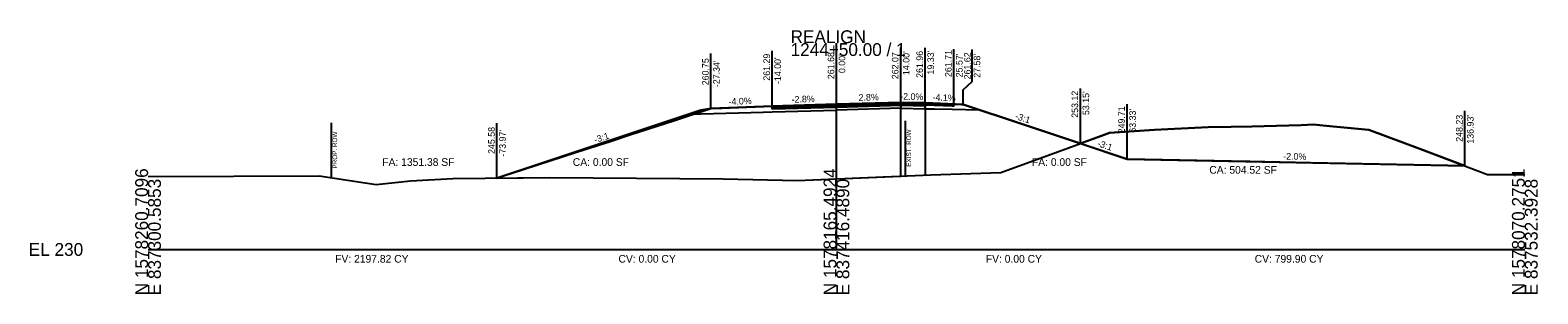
# Model space of a CAD drawing. Extents: x -26 to 6303, y -16 to 9563.
# Drawn here: x 1974.3 to 2302.8, y 5490.3 to 5547.8 of the extents above; entities that cross this region are included whole.
import ezdxf

# ---------------------------------------------------------------- set-up
doc = ezdxf.new("R2010")
doc.units = 0
for name, color, linetype in [('ASPHALT_19MM1', 7, 'Continuous'), ('ASPHALT_9_5MM1', 7, 'Continuous'), ('CONST_DCH', 7, 'Continuous'), ('CONST_LV3', 7, 'Continuous'), ('Draft_XS_Grid', 7, 'Continuous'), ('DTM_P_FINISHED_GRADE', 7, 'Continuous'), ('DTM_P_FINISHED_GRADE2', 7, 'Continuous'), ('DTM_TEMP_DROP', 7, 'Continuous'), ('DTM_X_GROUND', 7, 'Continuous'), ('TRANS_EOP_PAVED', 7, 'Continuous'), ('TRANS_PAVED_SHOULDERS', 7, 'Continuous'), ('XS_CELL', 7, 'Continuous'), ('XS_M_SHAPES_EARTHWORK', 7, 'Continuous'), ('XS_P_ASPHALT', 7, 'Continuous'), ('XS_P_GROUND', 7, 'Continuous'), ('XS_P_ROW', 7, 'Continuous'), ('XS_P_SHOULDER', 7, 'Continuous'), ('XS_P_SUBGRADE_GRANULAR', 7, 'Continuous'), ('XS_P_TX_CLEARZONE', 7, 'Continuous'), ('XS_P_TX_FS_BS', 7, 'Continuous'), ('XS_SHEET_EW_TX_AREA', 7, 'Continuous'), ('XS_SHEET_EW_TX_VOLUME', 7, 'Continuous'), ('XS_X_ROW', 7, 'Continuous')]:
    doc.layers.add(name, color=color, linetype=linetype)

msp = doc.modelspace()

# ---------------------------------------------------------------- linework, layer by layer
at = {"layer": 'ASPHALT_19MM1'}
for points in [[(2136, 5530.95), (2136, 5530.68), (2150, 5531.07), (2150, 5531.07), (2164, 5531.47), (2164, 5531.47), (2164, 5531.74), (2164, 5531.74), (2164, 5531.74), (2150, 5531.34), (2150, 5531.34), (2136, 5530.95), (2136, 5530.95)], [(2164, 5531.74), (2164, 5531.46), (2164, 5531.46), (2164, 5531.46), (2169.33, 5531.36), (2169.33, 5531.63), (2164, 5531.74), (2164, 5531.74), (2164, 5531.74)]]:
    msp.add_lwpolyline(points, dxfattribs=at)
at = {"layer": 'ASPHALT_9_5MM1'}
for points in [[(2136, 5531.29), (2136, 5531.16), (2150, 5531.55), (2150, 5531.55), (2164, 5531.94), (2164, 5531.94), (2164, 5532.07), (2164, 5532.07), (2164, 5532.07), (2150, 5531.68), (2150, 5531.68), (2136, 5531.29), (2136, 5531.29)], [(2164, 5532.07), (2164, 5531.94), (2164, 5531.94), (2164, 5531.94), (2169.33, 5531.84), (2169.33, 5531.96), (2164, 5532.07), (2164, 5532.07), (2164, 5532.07)]]:
    msp.add_lwpolyline(points, dxfattribs=at)
at = {"layer": 'CONST_LV3'}
for points in [[(2169.33, 5531.96), (2164, 5532.07), (2164, 5532.07), (2164, 5532.07), (2150, 5531.68)], [(2164, 5532.07), (2164, 5530.8), (2164, 5530.8), (2164, 5530.8), (2169.33, 5530.69), (2169.33, 5531.96), (2164, 5532.07), (2164, 5532.07), (2164, 5532.07)], [(2177.58, 5531.62), (2169.33, 5531.96), (2169.33, 5531.96)]]:
    msp.add_lwpolyline(points, dxfattribs=at)
at = {"layer": 'DTM_P_FINISHED_GRADE'}
msp.add_lwpolyline([(2164, 5532.07), (2164, 5532.07), (2169.33, 5531.96)], dxfattribs=at)
at = {"layer": 'DTM_P_FINISHED_GRADE2'}
msp.add_lwpolyline([(2076.03, 5515.58), (2076.59, 5515.76), (2077.46, 5516.04), (2081.71, 5517.42), (2084.88, 5518.45), (2087.52, 5519.31), (2093.35, 5521.2), (2094.96, 5521.72), (2100.92, 5523.65), (2105.01, 5524.99), (2114.68, 5528.15), (2116.68, 5528.8), (2122.66, 5530.75), (2125.05, 5530.85), (2136, 5531.29), (2136, 5531.29), (2150, 5531.68), (2164, 5532.07), (2164, 5532.07), (2169.33, 5531.96), (2175.25, 5531.72), (2175.46, 5531.71), (2175.57, 5531.71), (2177.23, 5531.64), (2177.58, 5531.62), (2190.75, 5527.24), (2194.45, 5526.01), (2197.53, 5524.98), (2203.15, 5523.12)], dxfattribs=at)
at = {"layer": 'DTM_X_GROUND'}
msp.add_lwpolyline([(2000, 5515.93), (2037.27, 5516.06), (2047.33, 5514.54), (2049.68, 5514.16), (2057.22, 5514.98), (2066.4, 5515.5), (2087.54, 5515.68), (2125.3, 5515.39), (2141.42, 5515.05), (2170.56, 5516.28), (2185.84, 5516.81), (2208.34, 5525), (2209.53, 5525.43), (2219.32, 5526.08), (2230.97, 5526.67), (2236.04, 5526.76), (2240.49, 5526.83), (2251.27, 5527.14), (2253.99, 5527.22), (2256.7, 5526.96), (2266.03, 5526.11), (2277.14, 5521.95), (2291.88, 5516.36), (2296.27, 5516.36), (2300, 5516.38)], dxfattribs=at)
at = {"layer": 'TRANS_PAVED_SHOULDERS'}
for points in [[(2136, 5531.16), (2136, 5530.95), (2150, 5531.34), (2150, 5531.34), (2164, 5531.74), (2164, 5531.74), (2164, 5531.94), (2164, 5531.94), (2164, 5531.94), (2150, 5531.55), (2150, 5531.55), (2136, 5531.16), (2136, 5531.16)], [(2164, 5531.94), (2164, 5531.74), (2164, 5531.74), (2164, 5531.74), (2169.33, 5531.63), (2169.33, 5531.84), (2164, 5531.94), (2164, 5531.94), (2164, 5531.94)]]:
    msp.add_lwpolyline(points, dxfattribs=at)
at = {"layer": 'XS_CELL'}
for p, q in [((2150, 5500), (2150, 5545)), ((2000, 5500), (2150, 5500)), ((2150, 5500), (2300, 5500))]:
    msp.add_line(p, q, dxfattribs=at)
at = {"layer": 'XS_M_SHAPES_EARTHWORK'}
for points in [[(2076.03, 5515.58), (2087.54, 5515.68), (2125.3, 5515.39), (2141.42, 5515.05), (2164, 5516.01), (2164, 5531.47), (2150, 5531.07), (2136, 5530.68), (2136, 5530.95), (2136, 5531.16), (2136, 5531.29), (2122.66, 5530.75), (2120.43, 5530.38), (2117.8, 5529.51)], [(2169.33, 5531.56), (2169.33, 5516.23), (2170.56, 5516.28), (2185.84, 5516.81), (2203.15, 5523.12), (2198.4, 5524.69), (2194.46, 5526.01), (2186.83, 5528.55), (2181.13, 5530.44), (2177.58, 5531.62), (2175.57, 5531.71), (2175.57, 5531.31), (2175.25, 5531.32)]]:
    msp.add_lwpolyline(points, close=True, dxfattribs=at)
at = {"layer": 'XS_P_ASPHALT'}
for points in [[(2164, 5532.07), (2164, 5532.07), (2164, 5532.07), (2169.33, 5531.96)], [(2169.33, 5531.96), (2169.33, 5531.56), (2169.33, 5531.56), (2175.25, 5531.32), (2175.57, 5531.31), (2175.57, 5531.71), (2175.25, 5531.72), (2169.33, 5531.96), (2169.33, 5531.96)]]:
    msp.add_lwpolyline(points, dxfattribs=at)
at = {"layer": 'XS_P_GROUND'}
for points in [[(2122.66, 5530.75), (2120.43, 5530.38), (2076.03, 5515.58)], [(2177.58, 5531.62), (2186.83, 5528.55), (2194.46, 5526.01), (2198.4, 5524.69), (2203.15, 5523.12)], [(2213.33, 5519.71), (2204.44, 5522.67), (2204.44, 5522.67), (2203.95, 5522.83), (2203.95, 5522.83), (2203.94, 5522.83), (2203.92, 5522.84), (2203.43, 5523.01), (2203.43, 5523.01), (2202.95, 5523.17), (2202.95, 5523.17), (2202.72, 5523.24), (2202.72, 5523.24), (2202.48, 5523.32), (2202.48, 5523.32), (2202.47, 5523.33), (2201.7, 5523.58), (2201.7, 5523.58), (2201.48, 5523.66), (2201.48, 5523.66), (2201.42, 5523.68), (2201.34, 5523.7), (2201.34, 5523.7), (2201.05, 5523.8), (2201.05, 5523.8), (2201.05, 5523.8), (2200.43, 5524), (2200.43, 5524), (2200.04, 5524.14), (2200.04, 5524.14), (2199.91, 5524.18), (2199.91, 5524.18), (2199.78, 5524.22), (2199.78, 5524.22), (2199.77, 5524.23), (2199.65, 5524.27), (2199.65, 5524.27), (2199.65, 5524.27), (2199.63, 5524.27), (2199.13, 5524.44), (2199.13, 5524.44), (2198.65, 5524.6), (2198.65, 5524.6), (2198.48, 5524.66), (2198.48, 5524.66), (2198.3, 5524.72), (2198.3, 5524.72), (2198.28, 5524.72), (2197.79, 5524.89), (2197.79, 5524.89), (2197.32, 5525.04), (2197.32, 5525.04), (2197.17, 5525.09), (2197.17, 5525.09), (2197.02, 5525.14), (2197.02, 5525.14), (2196.52, 5525.31), (2196.52, 5525.31), (2196.07, 5525.46), (2196.07, 5525.46), (2195.94, 5525.5), (2195.94, 5525.5), (2195.82, 5525.54), (2195.82, 5525.54), (2195.8, 5525.55), (2195.33, 5525.71), (2195.33, 5525.71), (2194.9, 5525.85), (2194.9, 5525.85), (2194.79, 5525.89), (2194.79, 5525.89), (2194.69, 5525.92), (2194.69, 5525.92), (2194.67, 5525.92), (2194.66, 5525.93), (2194.22, 5526.07), (2194.22, 5526.07), (2194.22, 5526.07), (2193.82, 5526.21), (2193.82, 5526.21), (2193.73, 5526.24), (2193.73, 5526.24), (2193.64, 5526.27), (2193.64, 5526.27), (2193.21, 5526.41), (2193.21, 5526.41), (2192.84, 5526.53), (2192.84, 5526.53), (2192.77, 5526.56), (2192.7, 5526.58), (2192.69, 5526.59), (2192.69, 5526.59), (2192.3, 5526.72), (2192.3, 5526.72), (2191.97, 5526.83), (2191.91, 5526.85), (2191.85, 5526.87), (2191.84, 5526.87), (2191.84, 5526.87), (2191.84, 5526.87), (2188.38, 5528.02), (2188.38, 5528.02), (2186.82, 5528.54), (2186.82, 5528.54), (2177.76, 5531.56), (2177.76, 5531.56), (2177.58, 5531.62)], [(2240.07, 5519.17), (2236.08, 5519.25), (2236.08, 5519.25), (2221.07, 5519.55), (2221.07, 5519.55), (2221.07, 5519.55), (2213.33, 5519.71)], [(2286.93, 5518.23), (2253.27, 5518.91), (2240.07, 5519.17)]]:
    msp.add_lwpolyline(points, dxfattribs=at)
at = {"layer": 'XS_P_ROW'}
msp.add_line((2040, 5515.65), (2040, 5527.65), dxfattribs=at)
at = {"layer": 'XS_P_SHOULDER'}
for points in [[(2122.66, 5530.75), (2136, 5531.29), (2136, 5531.29)], [(2169.33, 5531.96), (2169.33, 5531.96), (2175.25, 5531.72), (2177.58, 5531.62)]]:
    msp.add_lwpolyline(points, dxfattribs=at)
at = {"layer": 'XS_P_SUBGRADE_GRANULAR'}
for points in [[(2117.8, 5529.51), (2134, 5529.96), (2134, 5529.96), (2136, 5530.01), (2136, 5530.01)], [(2136, 5530.01), (2150, 5530.41), (2150, 5530.41)], [(2164, 5530.8), (2164, 5530.8), (2150, 5530.41)], [(2164, 5530.8), (2164, 5530.8), (2164, 5530.8), (2169.33, 5530.69)], [(2169.33, 5530.69), (2169.33, 5530.69), (2171.34, 5530.65), (2175.25, 5530.57), (2181.13, 5530.44)]]:
    msp.add_lwpolyline(points, dxfattribs=at)
at = {"layer": 'XS_P_TX_CLEARZONE'}
for p, q in [((2122.66, 5530.75), (2122.66, 5542.75)), ((2136, 5531.29), (2136, 5543.29)), ((2150, 5531.68), (2150, 5543.68)), ((2164, 5532.07), (2164, 5544.07)), ((2169.33, 5531.96), (2169.33, 5543.96)), ((2175.57, 5531.71), (2175.57, 5543.71)), ((2179.57, 5536.65), (2179.57, 5543.62)), ((2177.58, 5534.8), (2179.57, 5536.65)), ((2177.58, 5531.62), (2177.58, 5534.8)), ((2203.15, 5523.12), (2203.15, 5535.12)), ((2213.33, 5519.71), (2213.33, 5531.71)), ((2286.93, 5518.23), (2286.93, 5530.23)), ((2076.03, 5515.58), (2076.03, 5527.58))]:
    msp.add_line(p, q, dxfattribs=at)
at = {"layer": 'XS_P_TX_FS_BS'}
for p, q in [((2203.15, 5523.12), (2213.33, 5519.71)), ((2213.33, 5519.71), (2286.93, 5518.23))]:
    msp.add_line(p, q, dxfattribs=at)
msp.add_lwpolyline([(2286.93, 5518.23), (2277.14, 5521.95), (2266.03, 5526.11), (2256.7, 5526.96), (2253.99, 5527.22), (2251.27, 5527.14), (2240.49, 5526.83), (2236.04, 5526.76), (2230.97, 5526.67), (2219.32, 5526.08), (2209.53, 5525.43), (2208.34, 5525), (2203.15, 5523.12)], dxfattribs=at)
at = {"layer": 'XS_X_ROW'}
msp.add_line((2165.07, 5516.05), (2165.07, 5528.05), dxfattribs=at)

# ---------------------------------------------------------------- texts
at = {"layer": 'CONST_DCH'}
for p in [(2135.92, 5531.17), (2149.92, 5531.56), (2163.92, 5531.95), (2175.49, 5531.59), (2213.25, 5519.59)]:
    msp.add_text('X', height=0.24, dxfattribs=at).set_placement(p)
at = {"layer": 'CONST_LV3'}
msp.add_text('X', height=0.24, dxfattribs=at).set_placement((2177.5, 5531.5))
at = {"layer": 'Draft_XS_Grid'}
msp.add_text('-', height=0.0001, dxfattribs=at).set_placement((2000, 5500))
at = {"layer": 'DTM_TEMP_DROP'}
for p in [(2203.07, 5523), (2075.95, 5515.46)]:
    msp.add_text('X', height=0.24, dxfattribs=at).set_placement(p)
at = {"layer": 'TRANS_EOP_PAVED'}
for p in [(2177.5, 5531.5), (2203.07, 5523), (2075.95, 5515.46)]:
    msp.add_text('X', height=0.24, dxfattribs=at).set_placement(p)
at = {"layer": 'XS_CELL'}
for s, p in [('REALIGN', (2140, 5545)), ('1244+50.00 / 1', (2140, 5542.2)), ('EL 230', (1974, 5498.6))]:
    msp.add_text(s, height=2.8, dxfattribs=at).set_placement(p)
for s, p in [('N 1578260.7096', (2000, 5490)), ('N 1578165.4924', (2150, 5490)), ('N 1578070.2751', (2300, 5490)), ('E 837300.5853', (2002.8, 5490)), ('E 837416.4890', (2152.8, 5490)), ('E 837532.3928', (2302.8, 5490))]:
    msp.add_text(s, height=2.8, rotation=90, dxfattribs=at).set_placement(p)
at = {"layer": 'XS_P_ASPHALT'}
msp.add_text('X', height=0.24, dxfattribs=at).set_placement((2286.85, 5518.11))
at = {"layer": 'XS_P_ROW'}
msp.add_text('PROP. ROW', height=1, rotation=90, dxfattribs=at).set_placement((2041.2, 5517.65))
at = {"layer": 'XS_P_SUBGRADE_GRANULAR'}
for p in [(2122.58, 5530.63), (2169.25, 5531.84), (2177.5, 5531.5)]:
    msp.add_text('X', height=0.24, dxfattribs=at).set_placement(p)
at = {"layer": 'XS_P_TX_CLEARZONE'}
for s, p in [('261.29', (2135.52, 5536.81)), ('261.68', (2149.52, 5537.15)), ("0.00'", (2151.92, 5538.47)), ('262.07', (2163.52, 5537.13)), ("14.00'", (2165.92, 5538.04)), ('261.96', (2168.85, 5537.42)), ("19.33'", (2171.25, 5538.16)), ('261.71', (2175.09, 5537.61)), ("25.57'", (2177.49, 5537.54)), ('261.62', (2179.25, 5537.1)), ("27.58'", (2181.35, 5537.46)), ('260.75', (2122.18, 5535.82)), ("-27.34'", (2124.58, 5535.41)), ("-14.00'", (2137.92, 5536.08)), ('253.12', (2202.67, 5528.72)), ("53.15'", (2205.07, 5529.31)), ('249.71', (2212.85, 5525.32)), ("63.33'", (2215.25, 5525.47)), ('248.23', (2286.45, 5523.48)), ("136.93'", (2288.85, 5523.07)), ('245.58', (2075.55, 5520.83)), ("-73.97'", (2077.95, 5520.24))]:
    msp.add_text(s, height=1.44, rotation=90, dxfattribs=at).set_placement(p)
at = {"layer": 'XS_P_TX_FS_BS'}
for s, rotation, p in [('-4.0%', 2.2906, (2126.52, 5531.51)), ('-2.8%', 1.6039, (2140.25, 5532)), ('2.8%', 1.6039, (2154.84, 5532.41)), ('-2.0%', 358.8475, (2163.88, 5532.67)), ('-4.1%', 357.6425, (2170.92, 5532.5)), ('-3:1', 341.5974, (2188.83, 5528.51)), ('-3:1', 18.0207, (2097.43, 5523.18)), ('-3:1', 341.4838, (2206.71, 5522.56)), ('-2.0%', 358.8542, (2247.35, 5519.63))]:
    msp.add_text(s, height=1.44, rotation=rotation, dxfattribs=at).set_placement(p)
at = {"layer": 'XS_SHEET_EW_TX_AREA'}
for s, p in [('FA: 1351.38 SF', (2051.03, 5518.22)), ('CA: 0.00 SF', (2092.56, 5518.22)), ('FA: 0.00 SF', (2192.6, 5518.22)), ('CA: 504.52 SF', (2231.25, 5516.52))]:
    msp.add_text(s, height=1.68, dxfattribs=at).set_placement(p)
at = {"layer": 'XS_SHEET_EW_TX_VOLUME'}
for s, p in [('FV: 2197.82 CY', (2040.77, 5497.12)), ('CV: 0.00 CY', (2102.51, 5497.12)), ('FV: 0.00 CY', (2182.55, 5497.12)), ('CV: 799.90 CY', (2241.14, 5497.12))]:
    msp.add_text(s, height=1.68, dxfattribs=at).set_placement(p)
at = {"layer": 'XS_X_ROW'}
msp.add_text('EXIST. ROW', height=1, rotation=90, dxfattribs=at).set_placement((2166.27, 5518.05))

doc.saveas('drawing.dxf')
